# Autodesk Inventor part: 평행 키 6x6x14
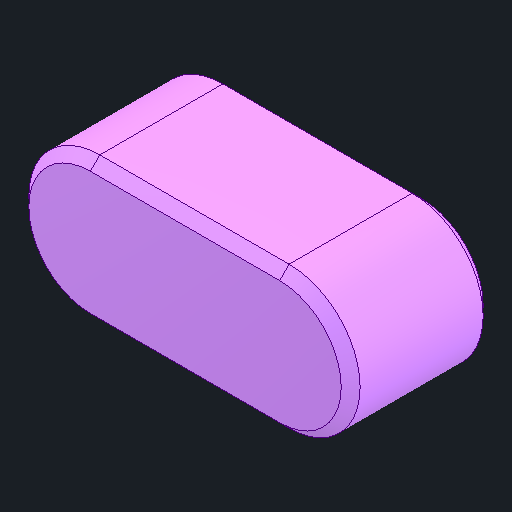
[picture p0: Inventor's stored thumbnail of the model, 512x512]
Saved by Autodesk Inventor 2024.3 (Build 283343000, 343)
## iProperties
Created: 2025-07
Part Number: 평행 키 6x6x14
Material: 강철, 연강
Description: 키 및 해당 키홈
Document SubType Name: Modeling
Designer: user
Density: 7.85 g/cm^3
Appearance: 기본값
Author: jhkim
Sending System: Autodesk Inventor 2026
Preprocessor: ST-DEVELOPER v20.1
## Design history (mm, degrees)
feature "Solid1"
node "솔리드1"
